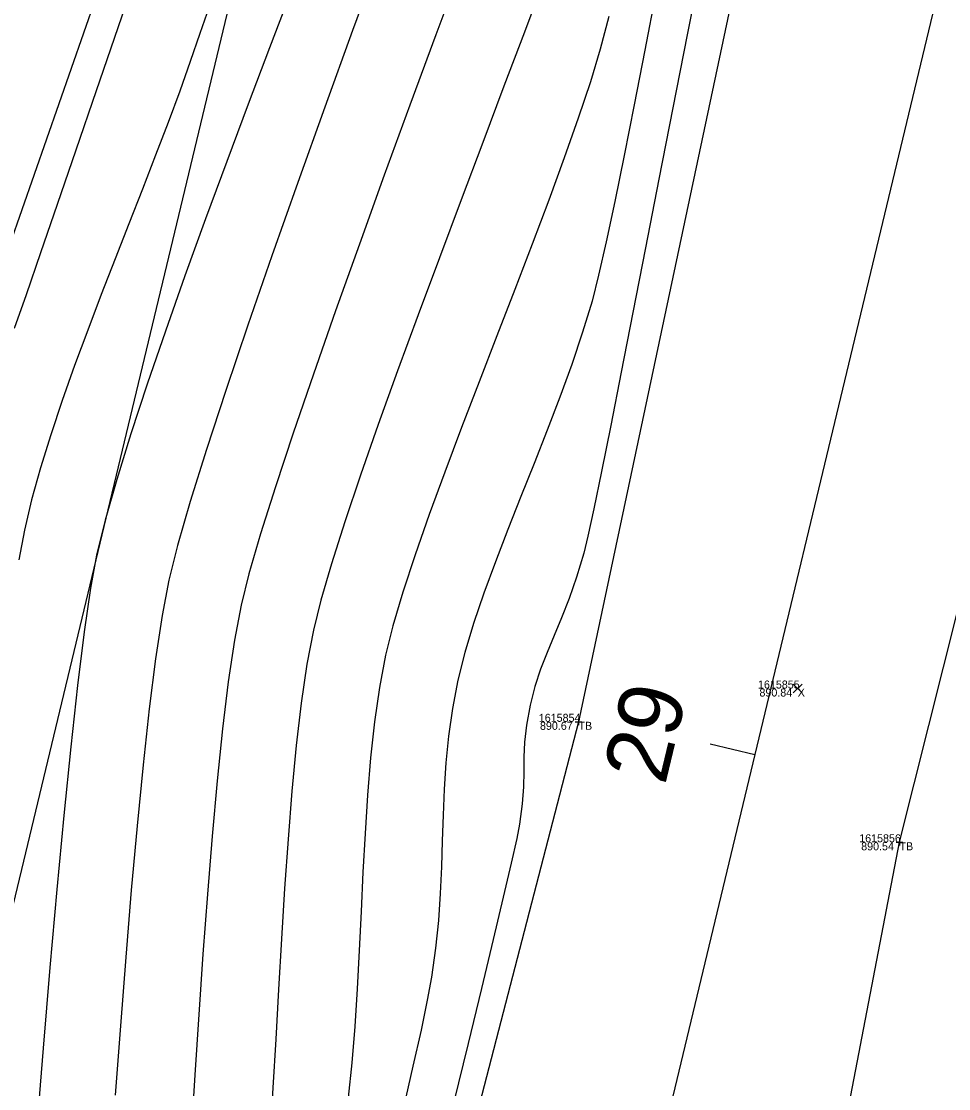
# Model space of a CAD drawing. Extents: x 1957117 to 1971063, y 701601 to 715861.
# Drawn here: x 1963009.26 to 1963049.81, y 704853.18 to 704899.84 of the extents above; entities that cross this region are included whole.
import ezdxf

# ---------------------------------------------------------------- set-up
doc = ezdxf.new("R2010")
doc.units = 0
for name, color, linetype in [('AP_X_Lights', 7, 'Continuous'), ('DT_X_Break_Line', 7, 'Continuous'), ('DT_X_Contour_Major', 7, 'Continuous'), ('DT_X_Contour_Minor', 7, 'Continuous'), ('GE_X_CL_20', 7, 'Continuous'), ('HY_X_Water_Edge', 7, 'Continuous'), ('PV_P_Drive', 7, 'Continuous'), ('PV_P_Shoulder', 7, 'Continuous'), ('RS_Raster1', 7, 'Continuous'), ('RW_X_Esmt_RR', 7, 'Continuous'), ('SC_Scratch1', 7, 'Continuous'), ('SC_Shading5', 7, 'Continuous')]:
    doc.layers.add(name, color=color, linetype=linetype)

msp = doc.modelspace()

# ---------------------------------------------------------------- linework, layer by layer
at = {"layer": 'AP_X_Lights'}
for p, q in [((1963043.018, 704870.479), (1963043.406, 704870.869)), ((1963043.018, 704870.869), (1963043.406, 704870.479))]:
    msp.add_line(p, q, dxfattribs=at)
at = {"layer": 'DT_X_Break_Line'}
for points in [[(1962854.549, 704243.654), (1962868.069, 704295.231), (1962879.669, 704344.313), (1962892.757, 704392.318), (1962905.964, 704443.142), (1962917.718, 704492.375), (1962926.962, 704538.336), (1962936.778, 704587.265), (1962949.215, 704630.669), (1962963.968, 704683.754), (1962972.038, 704733.348), (1962988.206, 704780.999), (1962994.689, 704830.943), (1963004.932, 704879.138), (1963021.822, 704927.498), (1963031.944, 704976.286), (1963045.21, 705027.355), (1963059.618, 705072.384), (1963067.267, 705121.949)], [(1962898.502, 704228.866), (1962909.862, 704285.214), (1962922.189, 704334.068), (1962935.173, 704382.087), (1962941.87, 704432.109), (1962957.87, 704479.084), (1962969.135, 704528.545), (1962980.039, 704577.268), (1962992.03, 704625.595), (1963002.128, 704674.596), (1963014.376, 704720.299), (1963028.69, 704776.02), (1963039.098, 704819.371), (1963047.66, 704863.952), (1963060.514, 704915.168), (1963074.044, 704961.959), (1963084.157, 705010.121), (1963093.862, 705036.7), (1963097.69, 705062.728), (1963110.134, 705110.941)], [(1963081.686, 705067.168), (1963070.617, 705018.992), (1963060.629, 704969.66), (1963044.793, 704921.859), (1963033.624, 704869.219), (1963022.038, 704824.561), (1963012.554, 704778.141), (1962998.858, 704727.004), (1962987.967, 704677.611), (1962975.675, 704626.305), (1962966.447, 704580.213), (1962950.262, 704533.092), (1962939.515, 704481.257), (1962926.044, 704436.037), (1962917.68, 704386.811), (1962906.11, 704337.415), (1962892.064, 704289.931), (1962881.011, 704234.451)]]:
    msp.add_lwpolyline(points, dxfattribs=at)
at = {"layer": 'DT_X_Contour_Major'}
for points in [[(1963024.975, 704902.795), (1963023.749, 704899.446), (1963022.534, 704896.096), (1963021.351, 704892.796), (1963020.221, 704889.597), (1963019.164, 704886.552), (1963018.201, 704883.71), (1963017.354, 704881.124), (1963016.642, 704878.845), (1963016.088, 704876.923), (1963015.711, 704875.412), (1963015.419, 704873.865), (1963015.134, 704871.973), (1963014.855, 704869.781), (1963014.585, 704867.334), (1963014.323, 704864.679), (1963014.07, 704861.861), (1963013.826, 704858.927), (1963013.593, 704855.922), (1963013.369, 704852.892)], [(1963024.975, 704902.795), (1963023.749, 704899.446), (1963022.534, 704896.096), (1963021.351, 704892.796), (1963020.221, 704889.597), (1963019.164, 704886.552), (1963018.201, 704883.71), (1963017.354, 704881.124), (1963016.642, 704878.845), (1963016.088, 704876.923), (1963015.711, 704875.412), (1963015.419, 704873.865), (1963015.134, 704871.973), (1963014.855, 704869.781), (1963014.585, 704867.334), (1963014.323, 704864.679), (1963014.07, 704861.861), (1963013.826, 704858.927), (1963013.593, 704855.922), (1963013.369, 704852.892)], [(1963039.013, 704902.474), (1963038.379, 704899.258), (1963037.752, 704896.063), (1963037.142, 704892.94), (1963036.557, 704889.939), (1963036.005, 704887.11), (1963035.495, 704884.505), (1963035.035, 704882.174), (1963034.634, 704880.167), (1963034.299, 704878.535), (1963034.039, 704877.329), (1963033.862, 704876.599), (1963033.54, 704875.541), (1963033.209, 704874.607), (1963032.878, 704873.767), (1963032.554, 704872.991), (1963032.247, 704872.25), (1963031.964, 704871.516), (1963031.715, 704870.759), (1963031.507, 704869.951), (1963031.347, 704869.073), (1963031.267, 704868.333), (1963031.238, 704867.674), (1963031.23, 704867.042), (1963031.215, 704866.379), (1963031.164, 704865.63), (1963031.046, 704864.74), (1963030.921, 704864.115), (1963030.678, 704863.034), (1963030.331, 704861.548), (1963029.893, 704859.706), (1963029.376, 704857.559), (1963028.793, 704855.156), (1963028.158, 704852.547)], [(1963039.013, 704902.474), (1963038.379, 704899.258), (1963037.752, 704896.063), (1963037.142, 704892.94), (1963036.557, 704889.939), (1963036.005, 704887.11), (1963035.495, 704884.505), (1963035.035, 704882.174), (1963034.634, 704880.167), (1963034.299, 704878.535), (1963034.039, 704877.329), (1963033.862, 704876.599), (1963033.54, 704875.541), (1963033.209, 704874.607), (1963032.878, 704873.767), (1963032.554, 704872.991), (1963032.247, 704872.25), (1963031.964, 704871.516), (1963031.715, 704870.759), (1963031.507, 704869.951), (1963031.347, 704869.073), (1963031.267, 704868.333), (1963031.238, 704867.674), (1963031.23, 704867.042), (1963031.215, 704866.379), (1963031.164, 704865.63), (1963031.046, 704864.74), (1963030.921, 704864.115), (1963030.678, 704863.034), (1963030.331, 704861.548), (1963029.893, 704859.706), (1963029.376, 704857.559), (1963028.793, 704855.156), (1963028.158, 704852.547)]]:
    msp.add_lwpolyline(points, dxfattribs=at)
at = {"layer": 'DT_X_Contour_Minor'}
for points in [[(1963014.455, 704902.419), (1963013.477, 704899.551), (1963012.536, 704896.802), (1963011.648, 704894.216), (1963010.829, 704891.838), (1963010.096, 704889.714), (1963009.466, 704887.889), (1963008.954, 704886.41)], [(1963014.455, 704902.419), (1963013.477, 704899.551), (1963012.536, 704896.802), (1963011.648, 704894.216), (1963010.829, 704891.838), (1963010.096, 704889.714), (1963009.466, 704887.889), (1963008.954, 704886.41)], [(1963028.518, 704902.298), (1963027.39, 704899.256), (1963026.255, 704896.179), (1963025.133, 704893.112), (1963024.042, 704890.099), (1963023.002, 704887.186), (1963022.03, 704884.418), (1963021.147, 704881.839), (1963020.37, 704879.495), (1963019.72, 704877.43), (1963019.213, 704875.69), (1963018.87, 704874.319), (1963018.581, 704872.786), (1963018.31, 704870.967), (1963018.058, 704868.905), (1963017.822, 704866.643), (1963017.602, 704864.221), (1963017.395, 704861.682), (1963017.201, 704859.067), (1963017.018, 704856.419), (1963016.846, 704853.78), (1963016.681, 704851.191)], [(1963028.518, 704902.298), (1963027.39, 704899.256), (1963026.255, 704896.179), (1963025.133, 704893.112), (1963024.042, 704890.099), (1963023.002, 704887.186), (1963022.03, 704884.418), (1963021.147, 704881.839), (1963020.37, 704879.495), (1963019.72, 704877.43), (1963019.213, 704875.69), (1963018.87, 704874.319), (1963018.581, 704872.786), (1963018.31, 704870.967), (1963018.058, 704868.905), (1963017.822, 704866.643), (1963017.602, 704864.221), (1963017.395, 704861.682), (1963017.201, 704859.067), (1963017.018, 704856.419), (1963016.846, 704853.78), (1963016.681, 704851.191)], [(1963032.101, 704901.618), (1963031.258, 704899.374), (1963030.364, 704897.004), (1963029.434, 704894.545), (1963028.487, 704892.034), (1963027.539, 704889.508), (1963026.609, 704887.005), (1963025.713, 704884.561), (1963024.869, 704882.213), (1963024.094, 704880), (1963023.405, 704877.957), (1963022.82, 704876.123), (1963022.356, 704874.534), (1963022.03, 704873.227), (1963021.747, 704871.733), (1963021.5, 704870.04), (1963021.283, 704868.181), (1963021.093, 704866.187), (1963020.924, 704864.092), (1963020.774, 704861.927), (1963020.636, 704859.726), (1963020.508, 704857.52), (1963020.385, 704855.343), (1963020.262, 704853.225), (1963020.135, 704851.201)], [(1963032.101, 704901.618), (1963031.258, 704899.374), (1963030.364, 704897.004), (1963029.434, 704894.545), (1963028.487, 704892.034), (1963027.539, 704889.508), (1963026.609, 704887.005), (1963025.713, 704884.561), (1963024.869, 704882.213), (1963024.094, 704880), (1963023.405, 704877.957), (1963022.82, 704876.123), (1963022.356, 704874.534), (1963022.03, 704873.227), (1963021.747, 704871.733), (1963021.5, 704870.04), (1963021.283, 704868.181), (1963021.093, 704866.187), (1963020.924, 704864.092), (1963020.774, 704861.927), (1963020.636, 704859.726), (1963020.508, 704857.52), (1963020.385, 704855.343), (1963020.262, 704853.225), (1963020.135, 704851.201)], [(1963017.576, 704900.761), (1963017.073, 704899.312), (1963016.65, 704898.087), (1963016.189, 704896.788), (1963015.681, 704895.418), (1963015.133, 704893.987), (1963014.557, 704892.508), (1963013.962, 704890.993), (1963013.358, 704889.452), (1963012.756, 704887.897), (1963012.164, 704886.34), (1963011.592, 704884.792), (1963011.052, 704883.265), (1963010.552, 704881.771), (1963010.102, 704880.32), (1963009.712, 704878.924), (1963009.393, 704877.596), (1963009.153, 704876.3)], [(1963017.576, 704900.761), (1963017.073, 704899.312), (1963016.65, 704898.087), (1963016.189, 704896.788), (1963015.681, 704895.418), (1963015.133, 704893.987), (1963014.557, 704892.508), (1963013.962, 704890.993), (1963013.358, 704889.452), (1963012.756, 704887.897), (1963012.164, 704886.34), (1963011.592, 704884.792), (1963011.052, 704883.265), (1963010.552, 704881.771), (1963010.102, 704880.32), (1963009.712, 704878.924), (1963009.393, 704877.596), (1963009.153, 704876.3)], [(1963021.014, 704901.063), (1963020.11, 704898.685), (1963019.18, 704896.225), (1963018.243, 704893.719), (1963017.315, 704891.204), (1963016.415, 704888.719), (1963015.559, 704886.3), (1963014.765, 704883.985), (1963014.05, 704881.81), (1963013.431, 704879.814), (1963012.926, 704878.032), (1963012.552, 704876.504), (1963012.287, 704875.064), (1963012.008, 704873.147), (1963011.719, 704870.813), (1963011.422, 704868.119), (1963011.12, 704865.127), (1963010.815, 704861.894), (1963010.512, 704858.481), (1963010.212, 704854.946), (1963009.919, 704851.349)], [(1963021.014, 704901.063), (1963020.11, 704898.685), (1963019.18, 704896.225), (1963018.243, 704893.719), (1963017.315, 704891.204), (1963016.415, 704888.719), (1963015.559, 704886.3), (1963014.765, 704883.985), (1963014.05, 704881.81), (1963013.431, 704879.814), (1963012.926, 704878.032), (1963012.552, 704876.504), (1963012.287, 704875.064), (1963012.008, 704873.147), (1963011.719, 704870.813), (1963011.422, 704868.119), (1963011.12, 704865.127), (1963010.815, 704861.894), (1963010.512, 704858.481), (1963010.212, 704854.946), (1963009.919, 704851.349)], [(1963037.007, 704901.097), (1963036.525, 704898.582), (1963036.061, 704896.193), (1963035.623, 704893.974), (1963035.213, 704891.965), (1963034.839, 704890.207), (1963034.505, 704888.743), (1963034.217, 704887.613), (1963033.806, 704886.248), (1963033.333, 704884.845), (1963032.811, 704883.414), (1963032.256, 704881.967), (1963031.681, 704880.513), (1963031.102, 704879.064), (1963030.533, 704877.629), (1963029.988, 704876.219), (1963029.483, 704874.846), (1963029.032, 704873.518), (1963028.648, 704872.247), (1963028.348, 704871.043), (1963028.11, 704869.795), (1963027.94, 704868.591), (1963027.824, 704867.421), (1963027.75, 704866.274), (1963027.701, 704865.14), (1963027.666, 704864.01), (1963027.63, 704862.873), (1963027.579, 704861.719), (1963027.499, 704860.538), (1963027.377, 704859.32), (1963027.198, 704858.055), (1963027.013, 704857.053), (1963026.739, 704855.745), (1963026.386, 704854.168), (1963025.965, 704852.358)], [(1963037.007, 704901.097), (1963036.525, 704898.582), (1963036.061, 704896.193), (1963035.623, 704893.974), (1963035.213, 704891.965), (1963034.839, 704890.207), (1963034.505, 704888.743), (1963034.217, 704887.613), (1963033.806, 704886.248), (1963033.333, 704884.845), (1963032.811, 704883.414), (1963032.256, 704881.967), (1963031.681, 704880.513), (1963031.102, 704879.064), (1963030.533, 704877.629), (1963029.988, 704876.219), (1963029.483, 704874.846), (1963029.032, 704873.518), (1963028.648, 704872.247), (1963028.348, 704871.043), (1963028.11, 704869.795), (1963027.94, 704868.591), (1963027.824, 704867.421), (1963027.75, 704866.274), (1963027.701, 704865.14), (1963027.666, 704864.01), (1963027.63, 704862.873), (1963027.579, 704861.719), (1963027.499, 704860.538), (1963027.377, 704859.32), (1963027.198, 704858.055), (1963027.013, 704857.053), (1963026.739, 704855.745), (1963026.386, 704854.168), (1963025.965, 704852.358)], [(1963034.944, 704900.053), (1963034.571, 704898.628), (1963034.143, 704897.199), (1963033.615, 704895.604), (1963033.003, 704893.871), (1963032.325, 704892.026), (1963031.596, 704890.098), (1963030.834, 704888.112), (1963030.054, 704886.097), (1963029.274, 704884.078), (1963028.51, 704882.084), (1963027.778, 704880.14), (1963027.096, 704878.275), (1963026.479, 704876.514), (1963025.945, 704874.886), (1963025.509, 704873.418), (1963025.189, 704872.135), (1963024.921, 704870.723), (1963024.706, 704869.222), (1963024.535, 704867.647), (1963024.398, 704866.014), (1963024.289, 704864.34), (1963024.197, 704862.64), (1963024.116, 704860.931), (1963024.035, 704859.228), (1963023.947, 704857.548), (1963023.843, 704855.906), (1963023.715, 704854.318), (1963023.553, 704852.8)], [(1963034.944, 704900.053), (1963034.571, 704898.628), (1963034.143, 704897.199), (1963033.615, 704895.604), (1963033.003, 704893.871), (1963032.325, 704892.026), (1963031.596, 704890.098), (1963030.834, 704888.112), (1963030.054, 704886.097), (1963029.274, 704884.078), (1963028.51, 704882.084), (1963027.778, 704880.14), (1963027.096, 704878.275), (1963026.479, 704876.514), (1963025.945, 704874.886), (1963025.509, 704873.418), (1963025.189, 704872.135), (1963024.921, 704870.723), (1963024.706, 704869.222), (1963024.535, 704867.647), (1963024.398, 704866.014), (1963024.289, 704864.34), (1963024.197, 704862.64), (1963024.116, 704860.931), (1963024.035, 704859.228), (1963023.947, 704857.548), (1963023.843, 704855.906), (1963023.715, 704854.318), (1963023.553, 704852.8)]]:
    msp.add_lwpolyline(points, dxfattribs=at)
at = {"layer": 'GE_X_CL_20'}
msp.add_line((1963041.331, 704867.771), (1963039.386, 704868.238), dxfattribs=at)
msp.add_lwpolyline([(1963418.3, 706437.397), (1962895.621, 704261.062)], dxfattribs=at)
at = {"layer": 'HY_X_Water_Edge'}
msp.add_spline([(1963191.723, 701994.048), (1963062.047, 702441.167), (1962863.491, 703169.356), (1962827.53, 703438.691), (1962823.213, 703537.412), (1962817.962, 703593.874), (1962817.97, 703697.316), (1962828.582, 703804.235), (1962836.461, 703844.734), (1962850.687, 703896.004), (1962867.251, 703938.846), (1962873.848, 703992.355), (1962884.135, 704091.371), (1962891.241, 704140.854), (1962897.382, 704180.529), (1962905.467, 704230.979), (1962943.949, 704328.022), (1962948.537, 704378.842), (1962964.114, 704426.264), (1963004.885, 704570.73), (1963042.054, 704716.522), (1963062.038, 704814.417), (1963072.171, 704860.237), (1963090.023, 704956.798), (1963107.066, 705031.783), (1963133.773, 705105.742), (1963148.685, 705206.74), (1963175.48, 705301.059), (1963191.635, 705353.417), (1963210.988, 705447.286), (1963219.532, 705497.27), (1963230.124, 705549.475), (1963251.052, 705591.159), (1963275.289, 705693.429), (1963292.982, 705784.032), (1963302.841, 705839.645), (1963335.126, 705936.766), (1963359.752, 706046.75), (1963389.133, 706177.299), (1963417.827, 706273.456), (1963475.868, 706451.902), (1963533.782, 706640.53), (1963553.86, 706696.984), (1963580.184, 706715.425), (1963609.172, 706718.73), (1963617.062, 706714.691), (1963619.447, 706694.678), (1963564.282, 706533.07), (1963531.853, 706395.229), (1963434.4, 706006.96), (1963354.09, 705679.186), (1963237.513, 705206.07), (1963167.369, 704892.962), (1963059.145, 704434.176), (1962907.914, 703908.742), (1962877.458, 703703.326), (1962898.357, 703412.121), (1962942.65, 703052.267), (1963048.963, 702674.866), (1963191.468, 702189.666), (1963245.396, 702019.832)], degree=3, dxfattribs=at)
at = {"layer": 'PV_P_Drive'}
for p, q in [((1963033.478, 704869.219), (1963033.77, 704869.219)), ((1963033.624, 704869.365), (1963033.624, 704869.073)), ((1963033.624, 704869.219), (1963033.624, 704869.219)), ((1963047.514, 704863.952), (1963047.806, 704863.952)), ((1963047.66, 704864.098), (1963047.66, 704863.806)), ((1963047.66, 704863.952), (1963047.66, 704863.952))]:
    msp.add_line(p, q, dxfattribs=at)
at = {"layer": 'RW_X_Esmt_RR'}
msp.add_lwpolyline([(1962866.45, 704268.068), (1963123.345, 705337.727), (1963135.496, 705336.937), (1963400.797, 706441.601)], dxfattribs=at)
at = {"layer": 'SC_Shading5'}
for points in [[(1963026.912, 704294.121), (1963138.818, 704737.794), (1963251.679, 705213.963), (1963374.306, 705730.111), (1963454.783, 706045.593), (1963517.244, 706296.713), (1963562.763, 706479.256), (1963580.13, 706553.799), (1963589.678, 706586.994)], [(1963609.915, 706579.703), (1963587.283, 706499.153), (1963552.056, 706354.005), (1963480.911, 706069.234), (1963357.401, 705576.869), (1963272.751, 705226.931), (1963210.247, 704956.481), (1963044.97, 704288.881)]]:
    msp.add_spline(points, degree=3, dxfattribs=at)

# ---------------------------------------------------------------- texts
at = {"layer": 'GE_X_CL_20'}
msp.add_text('29', height=2.8, rotation=76.4953, dxfattribs=at).set_placement((1963037.403, 704866.406))
at = {"layer": 'PV_P_Shoulder'}
for s, p in [('890.84', (1963041.537, 704870.324)), ('890.67', (1963031.94, 704868.869)), ('890.54', (1963045.985, 704863.602))]:
    msp.add_text(s, height=0.35, dxfattribs=at).set_placement(p)
at = {"layer": 'RS_Raster1'}
for s, p in [('1615855', (1963041.473, 704870.674)), ('1615854', (1963031.888, 704869.219)), ('1615856', (1963045.899, 704863.952))]:
    msp.add_text(s, height=0.35, dxfattribs=at).set_placement(p)
at = {"layer": 'SC_Scratch1'}
for s, p in [('X', (1963043.212, 704870.324)), ('TB', (1963033.624, 704868.869)), ('TB', (1963047.66, 704863.602))]:
    msp.add_text(s, height=0.35, dxfattribs=at).set_placement(p)

doc.saveas('drawing.dxf')
